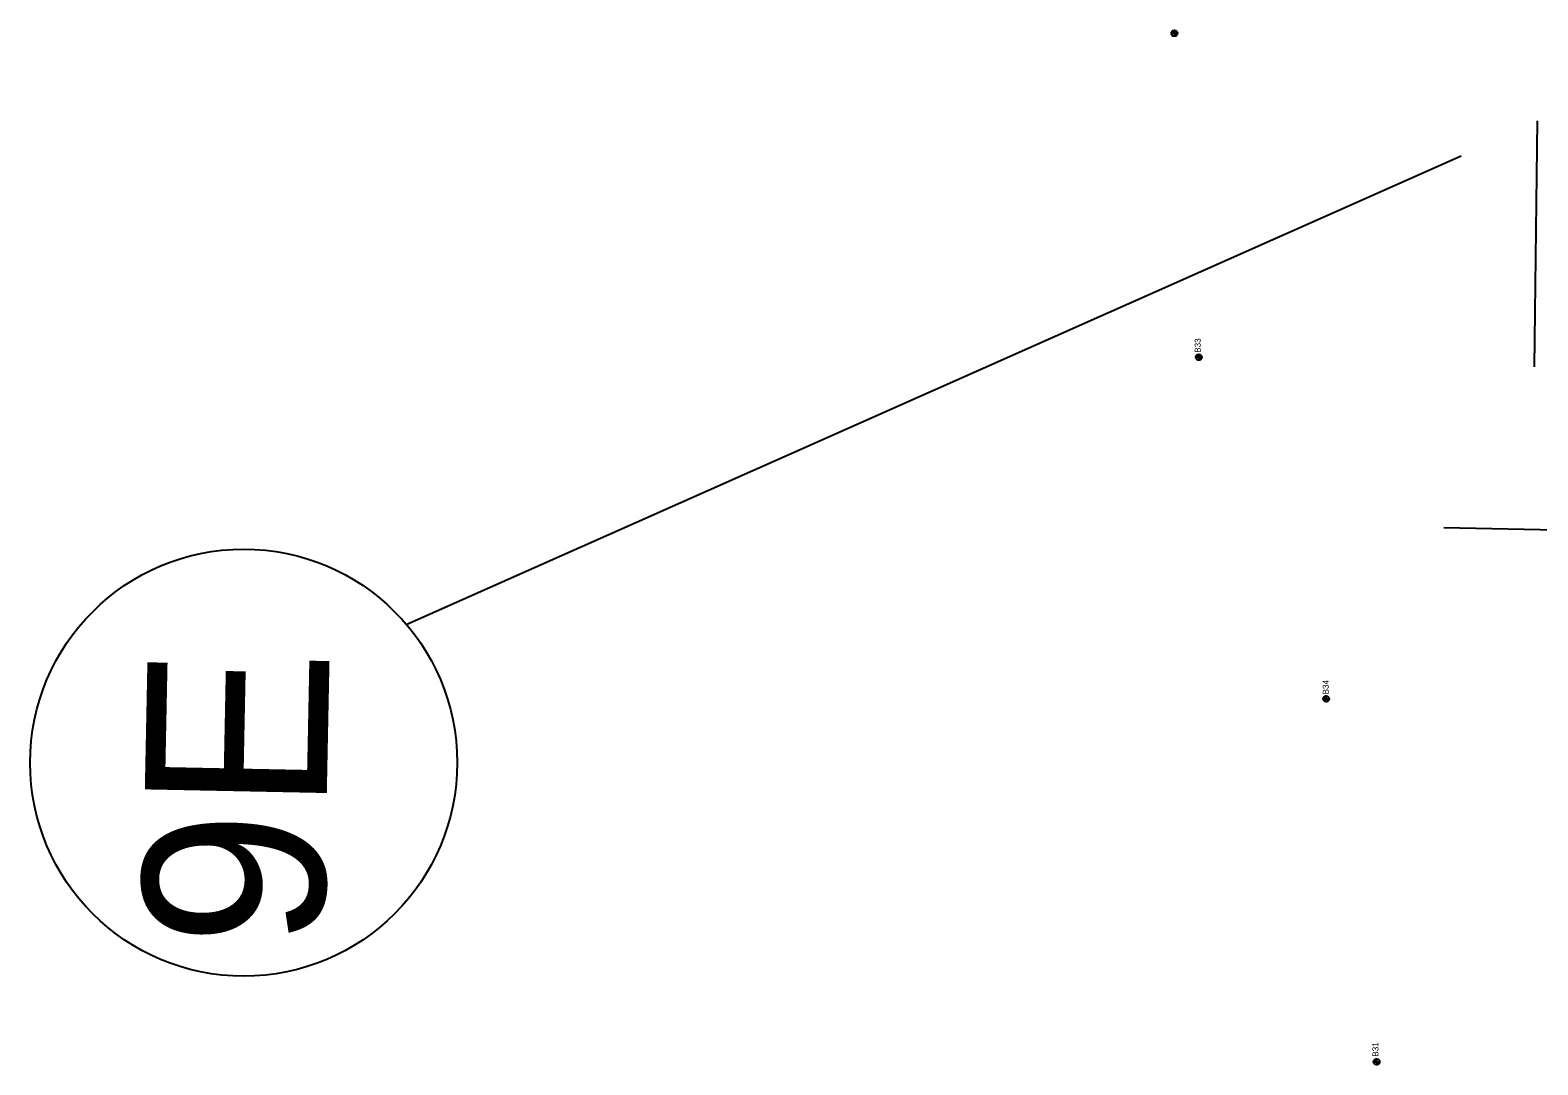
# Model space of a CAD drawing. Extents: x 311409 to 379449, y 121539 to 224848.
# Drawn here: x 359530 to 362015, y 146288 to 147993 of the extents above; entities that cross this region are included whole.
import ezdxf

# ---------------------------------------------------------------- set-up
doc = ezdxf.new("R2010")
doc.units = 0
for name, color, linetype in [('CA-TEXT', 7, 'Continuous'), ('E_SOIL_BORE1 [KAPUR_CADDS_LEVELS]', 7, 'Continuous'), ('E_SOIL_BORE2 [KAPUR_CADDS_LEVELS]', 7, 'Continuous'), ('P_MARK', 7, 'Continuous'), ('SIGNS-POLES', 7, 'Continuous')]:
    doc.layers.add(name, color=color, linetype=linetype)

msp = doc.modelspace()

# ---------------------------------------------------------------- linework, layer by layer
at = {"layer": 'CA-TEXT'}
msp.add_line((360149.9, 147014.1), (361888.3, 147785.8), dxfattribs=at)
msp.add_circle((359881.9, 146786.2), 351.8, dxfattribs=at)
at = {"layer": 'P_MARK'}
for p, q in [((361410.8, 147987.9), (361420.8, 147987.9)), ((361415.8, 147992.9), (361415.8, 147982.9)), ((361451, 147454.1), (361461, 147454.1)), ((361456, 147459.1), (361456, 147449.1)), ((361665.8, 146896.4), (361665.8, 146886.4)), ((361660.8, 146891.4), (361670.8, 146891.4)), ((361748.9, 146298.4), (361748.9, 146288.4)), ((361743.9, 146293.4), (361753.9, 146293.4))]:
    msp.add_line(p, q, dxfattribs=at)
for centre in [(361415.8, 147987.9), (361456, 147454.1), (361665.8, 146891.4), (361748.9, 146293.4)]:
    msp.add_circle(centre, 5, dxfattribs=at)
for centre, radius, start, end in [((361415.8, 147987.9), 4.5, 89.9869, 179.9869), ((361415.8, 147987.9), 4, 89.9869, 179.9869), ((361415.8, 147987.9), 3.5, 89.9869, 179.9869), ((361415.8, 147987.9), 3, 89.9869, 179.9869), ((361415.8, 147987.9), 2.5, 89.9869, 179.9869), ((361415.8, 147987.9), 2, 89.9869, 179.9869), ((361415.8, 147987.9), 1.5, 89.9869, 179.9869), ((361415.8, 147987.9), 1, 89.9869, 179.9869), ((361415.8, 147987.9), 0.5, 89.9869, 179.9869), ((361415.8, 147987.9), 4.5, 269.9869, 359.9869), ((361415.8, 147987.9), 4, 269.9869, 359.9869), ((361415.8, 147987.9), 3.5, 269.9869, 359.9869), ((361415.8, 147987.9), 3, 269.9869, 359.9869), ((361415.8, 147987.9), 2.5, 269.9869, 359.9869), ((361415.8, 147987.9), 2, 269.9869, 359.9869), ((361415.8, 147987.9), 1.5, 269.9869, 359.9869), ((361415.8, 147987.9), 1, 269.9869, 359.9869), ((361415.8, 147987.9), 0.5, 269.9869, 359.9869), ((361456, 147454.1), 4.5, 89.9869, 179.9869), ((361456, 147454.1), 4, 89.9869, 179.9869), ((361456, 147454.1), 3.5, 89.9869, 179.9869), ((361456, 147454.1), 3, 89.9869, 179.9869), ((361456, 147454.1), 2.5, 89.9869, 179.9869), ((361456, 147454.1), 2, 89.9869, 179.9869), ((361456, 147454.1), 1.5, 89.9869, 179.9869), ((361456, 147454.1), 1, 89.9869, 179.9869), ((361456, 147454.1), 0.5, 89.9869, 179.9869), ((361456, 147454.1), 4.5, 269.9869, 359.9869), ((361456, 147454.1), 4, 269.9869, 359.9869), ((361456, 147454.1), 3.5, 269.9869, 359.9869), ((361456, 147454.1), 3, 269.9869, 359.9869), ((361456, 147454.1), 2.5, 269.9869, 359.9869), ((361456, 147454.1), 2, 269.9869, 359.9869), ((361456, 147454.1), 1.5, 269.9869, 359.9869), ((361456, 147454.1), 1, 269.9869, 359.9869), ((361456, 147454.1), 0.5, 269.9869, 359.9869), ((361665.8, 146891.4), 4.5, 89.9869, 179.9869), ((361665.8, 146891.4), 4, 89.9869, 179.9869), ((361665.8, 146891.4), 3.5, 89.9869, 179.9869), ((361665.8, 146891.4), 3, 89.9869, 179.9869), ((361665.8, 146891.4), 2.5, 89.9869, 179.9869), ((361665.8, 146891.4), 2, 89.9869, 179.9869), ((361665.8, 146891.4), 1.5, 89.9869, 179.9869), ((361665.8, 146891.4), 1, 89.9869, 179.9869), ((361665.8, 146891.4), 0.5, 89.9869, 179.9869), ((361665.8, 146891.4), 4.5, 269.9869, 359.9869), ((361665.8, 146891.4), 4, 269.9869, 359.9869), ((361665.8, 146891.4), 3.5, 269.9869, 359.9869), ((361665.8, 146891.4), 3, 269.9869, 359.9869), ((361665.8, 146891.4), 2.5, 269.9869, 359.9869), ((361665.8, 146891.4), 2, 269.9869, 359.9869), ((361665.8, 146891.4), 1.5, 269.9869, 359.9869), ((361665.8, 146891.4), 1, 269.9869, 359.9869), ((361665.8, 146891.4), 0.5, 269.9869, 359.9869), ((361748.9, 146293.4), 4.5, 89.9869, 179.9869), ((361748.9, 146293.4), 4, 89.9869, 179.9869), ((361748.9, 146293.4), 3.5, 89.9869, 179.9869), ((361748.9, 146293.4), 3, 89.9869, 179.9869), ((361748.9, 146293.4), 2.5, 89.9869, 179.9869), ((361748.9, 146293.4), 2, 89.9869, 179.9869), ((361748.9, 146293.4), 1.5, 89.9869, 179.9869), ((361748.9, 146293.4), 1, 89.9869, 179.9869), ((361748.9, 146293.4), 0.5, 89.9869, 179.9869), ((361748.9, 146293.4), 4.5, 269.9869, 359.9869), ((361748.9, 146293.4), 4, 269.9869, 359.9869), ((361748.9, 146293.4), 3.5, 269.9869, 359.9869), ((361748.9, 146293.4), 3, 269.9869, 359.9869), ((361748.9, 146293.4), 2.5, 269.9869, 359.9869), ((361748.9, 146293.4), 2, 269.9869, 359.9869), ((361748.9, 146293.4), 1.5, 269.9869, 359.9869), ((361748.9, 146293.4), 1, 269.9869, 359.9869), ((361748.9, 146293.4), 0.5, 269.9869, 359.9869)]:
    msp.add_arc(centre, radius, start, end, dxfattribs=at)
at = {"layer": 'SIGNS-POLES'}
for p, q in [((362009.1, 147438.3), (362014.3, 147843.3)), ((362264.9, 147164.7), (361860, 147172.9))]:
    msp.add_line(p, q, dxfattribs=at)

# ---------------------------------------------------------------- texts
at = {"layer": 'CA-TEXT'}
msp.add_text('9E', height=300, rotation=88.8468, dxfattribs=at).set_placement((360013.8, 146480.2))
at = {"layer": 'E_SOIL_BORE1 [KAPUR_CADDS_LEVELS]'}
for s, p in [('B33', (361459.1, 147461.4)), ('B34', (361670.1, 146898.6))]:
    msp.add_text(s, height=10, rotation=89.9869, dxfattribs=at).set_placement(p)
at = {"layer": 'E_SOIL_BORE2 [KAPUR_CADDS_LEVELS]'}
msp.add_text('B31', height=10, rotation=89.9869, dxfattribs=at).set_placement((361752, 146301.8))

doc.saveas('drawing.dxf')
